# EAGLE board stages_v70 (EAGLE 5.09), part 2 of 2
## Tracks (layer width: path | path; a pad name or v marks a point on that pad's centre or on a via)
+3V3  (via drill 0.5)
  Top 0.254: IC5.19 15.75,59.58 15.86,59.69 18.24,59.69 v18.24,60.48 | v16.49,61.28 15.54,61.28 15.22,61.59 14.3,61.59 C11.1 | 21.73,59.69 | 24.11,61.61 24.05,61.67 IC5.1 | IC5.64 27.21,61.56 C14.1 | v19.51,54.93 v21.73,54.93 | v4.58,51.75 3.79,50.96 3.79,49.53 2.52,48.26 2.52,35.56 1.09,34.13 1.09,30.16 2.52,28.73 3,28.26 3,9.37 | v21.73,54.93 | v21.73,54.93 21.73,59.69 | v1.89,4.13 | v8.39,4.13 8.39,3.02 9.98,1.43 D9.2 | v1.89,4.13 3,5.24 3,9.37 | 3,9.37 | v27.76,56.04 28.75,57.03 R12.2
  Top 0.406: 18.24,59.69 | 18.24,59.69 21.73,59.69 23.65,61.61 24.11,61.61 24.12,61.59 26.02,61.59 26.65,62.23 | 41.92,64.74 v41.89,64.77 41.89,63.31 C10.1 42.49,62.71 C15.1 | v45.7,80.01 45.7,80.64 47.6,82.55 49.51,82.55 49.99,83.03 49.99,89.06 | 49.99,89.06 49.99,90.17 47.45,92.71 44.43,92.71 40.78,89.06 LED9.A | 49.99,89.06 LED8.A | 21.73,92.71 18.08,89.06 LED11.A | 21.73,92.71 | 21.73,92.71 24.59,92.71 28.24,89.06 LED10.A | IC2.3 42.49,58.16 C15.1 | C15.1 42.52,59.41 | 26.65,62.23 C9.1 26.65,62.83 C14.1 | 26.65,62.23 27.38,62.96 L2.2 28.62,63.02 32.84,63.02 33.63,63.82 34.59,63.82 v35.22,64.45
  Bottom 0.254: v16.49,61.28 17.12,61.28 17.92,60.48 v18.24,60.48 | v21.73,54.93 25.54,54.93 26.65,56.04 v27.76,56.04 | LED11.A 16.17,87.79 9.82,87.79 8.55,89.06 LED12.A | 56.65,87.95 58.24,87.95 | v19.51,54.93 17.28,52.7 15.86,52.7 15.22,53.34 6.17,53.34 v4.58,51.75 | v1.89,4.13 v8.39,4.13
  Bottom 0.356: LED10.A
  Bottom 0.406: v35.22,64.45 41.57,64.45 v41.89,64.77 45.7,68.58 v45.7,80.01 | 56.65,87.95 52.84,87.95 LED8.A | 58.24,87.95 59.35,89.06 LED7.A | LED10.A 29.98,87.95 39.19,87.95 LED9.A | LED9.A
+3V3_A  (via drill 0.5)
  Top 0.254: IC5.13 18.05,61.57 16.81,60.33 16.17,60.33 15.92,60.58 IC5.17 13.69,60.58 13.32,60.96 13.03,60.96 C13.1 C12.1 11.06,60.99 10.78,61.28 10.78,62.87 10.41,63.23 IC3.16 9.79,63.85 9.47,64.17 C7.1 9.51,64.81 v9.51,66.04 9.54,66.07 | v14.9,40.48 14.93,40.5 | v14.9,40.48 15.06,40.32 15.08,40.34 IC8.8 | v14.9,40.48 14.92,40.5 | IC10.8 61.11,40.34 60.95,40.5 v60.94,40.48 60.94,41.72 C34.1 | IC5.32 15,53.08 15.38,52.7 15.38,51.44 15.82,50.99 C24.1 | v16.17,53.66 16.17,53.02 15.82,52.67 C24.1 | IC9.8 37.9,40.34 v37.76,40.48 37.76,41.72 C30.1 | C16.1 v10.14,55.09 9.51,55.09 9.03,55.56 8.25,55.56 IC6.16 | v8.24,60.96 8.24,59.85 7.92,59.53 7.92,57.78 7.76,57.63 6.97,57.63 5.7,56.36 5.7,54.29 v5.22,53.82 | v5.22,53.82 | v14.9,40.48 14.9,41.75 | C24.1 15.97,50.95 IC5.33 | C24.1 C26.1 | IC4.2 36.33,54.38 36.33,55.09 36.81,55.56 40.3,55.56 40.62,55.24 C18.1
  Top 0.406: v4.11,99.69 7.6,103.19 v14.9,103.19 v26.33,103.19 v37.76,103.19 v49.19,103.19 v60.62,103.19 | R80.3 41.57,75.98 41.57,87.15 41.1,87.63 40.14,87.63 39.19,88.58 39.19,90.96 37.8,92.35 R86.P$1 | C33.1 14.9,41.75 14.9,41.74 | v8.71,70.64 8.71,69.85 9.98,68.58 9.98,67.97 C5.1 9.95,66.49 9.54,66.07 | R88.P$1 14.9,93.59 14.9,92.55 14.11,91.76 14.11,86.36 14.43,86.04 14.74,86.04 19.19,81.6 19.19,79.53 v18.71,79.06 | v66.02,91.12 66.02,86.2 64.91,85.09 64.91,81.44 64.43,80.96 64.43,79.85 62.84,78.26 59.83,78.26 58.4,76.83 53.95,76.83 53.08,75.96 R79.3 52.98,75.86 51.73,74.61 50.3,74.61 47.29,71.6 47.29,54.61 | v30.14,80.01 29.51,80.64 29.51,85.57 29.98,86.04 29.98,89.38 29.03,90.33 28.4,90.33 26.37,92.35 R87.P$1 | R78.3 61.91,46.02 59.99,47.94 58.56,47.94 58.08,48.42 52.68,48.42 51.28,49.82 C22.1 | C22.1 48.88,51.12 47.29,52.7 47.29,54.61 | C18.1 45.23,54.89 C20.1 45.57,54.61 47.29,54.61 | IC7.1 59.52,49.53 52.53,49.53 51.28,50.77 C22.1
  Bottom 0.254: v9.51,66.04 8.24,64.77 v8.24,60.96 | v16.17,53.66 16.01,53.82 10.14,53.82 | v5.22,53.82 10.14,53.82 | 10.14,53.82 v10.14,55.09
  Bottom 0.406: R89.P$1 3.47,93.67 3.47,99.06 v4.11,99.69 | v49.19,103.19 49.23,103.15 R85.P$1 | R86.P$1 37.76,93.67 v37.76,103.19 | R87.P$1 26.33,93.67 v26.33,103.19 | R88.P$1 14.9,93.67 v14.9,103.19 | v60.62,103.19 60.62,93.67 R84.P$1 60.66,91.72 61.89,90.49 65.39,90.49 v66.02,91.12 | 37.76,42.23 50.62,42.23 51.1,42.7 52.37,42.7 52.84,42.23 60.94,42.23 | 14.9,42.7 v14.9,40.48 | 14.9,42.7 17.76,42.7 18.24,42.23 27.76,42.23 28.24,42.7 29.67,42.7 30.14,42.23 37.76,42.23 | 37.76,42.23 | 37.76,42.23 v37.76,40.48 | 60.94,42.23 v60.94,40.48 | 60.94,42.23 60.94,44.45 61.91,45.42 R78.3 | v8.71,70.64 14.9,70.64 18.71,74.45 18.71,75.94 R82.3 18.69,79.04 v18.71,79.06 | R83.3 8.02,42.7 14.9,42.7 | v30.14,80.01 30.12,79.99 R81.3
ADC_CV_1  (via drill 0.5)
  Top 0.254: v14.9,44.61 14.9,46.35 16.97,48.42 16.97,49.21 17.05,49.3 IC5.34 | v57.13,45.72 59.19,43.66 59.19,43.18 59.51,42.86 R16.1 C35.2 62.21,41.72 62.21,41.27 62.53,40.96 63.48,40.96 63.8,40.64 63.8,40.01 63.49,39.7 IC10.7 | v57.13,45.72
  Bottom 0.254: v14.9,44.61 15.06,44.77 56.18,44.77 v57.13,45.72
ADC_CV_2  (via drill 0.5)
  Top 0.254: v19.19,43.81 17.44,45.56 17.44,49.05 17.55,49.16 IC5.35 | v57.13,44.29 57.76,44.29 58.36,43.69 R14.1 C32.2 58.36,40.8 58.08,40.52 IC10.1
  Bottom 0.254: v19.19,43.81 19.66,44.29 v57.13,44.29
ADC_CV_3  (via drill 0.5)
  Top 0.254: v12.84,49.53 12.36,50.01 12.36,53.82 13.13,54.58 IC5.29 | v40.3,48.58 40.3,45.09 39.07,43.85 R13.1 C31.2 39.07,41.24 39.35,40.96 40.3,40.96 40.62,40.64 40.62,40.01 40.31,39.7 IC9.7
  Bottom 0.254: v12.84,49.53 13.32,49.05 21.41,49.05 21.89,48.58 31.09,48.58 31.57,48.1 33.63,48.1 34.43,47.31 34.9,47.31 35.7,48.1 39.83,48.1 v40.3,48.58
ADC_CV_4  (via drill 0.5)
  Top 0.254: v13.32,50.8 12.84,51.28 12.84,53.66 13.26,54.08 IC5.30 | v34.59,48.42 35.38,47.62 35.38,43.01 35.24,42.86 R15.1 C29.2 35.19,40.8 IC9.1
  Bottom 0.254: v13.32,50.8 14.59,49.53 21.57,49.53 22.05,49.05 31.25,49.05 31.73,48.58 34.43,48.58 v34.59,48.42
ADC_CV_5
  Top 0.254: IC5.27 13.49,55.58 12.86,55.58 11.41,54.13 11.41,45.4 11.41,44.29 | IC8.7 17.45,39.7 17.76,40.01 17.76,40.64 17.44,40.96 16.49,40.96 16.21,41.24 R19.1 C27.2 12.84,42.86 11.89,43.81 | 11.41,44.29 | 11.41,44.29 | 11.41,44.29 | 11.89,43.81 11.41,44.29 | 11.89,43.81
ADC_CV_6
  Top 0.254: IC5.26 13.36,56.08 12.72,56.08 10.93,54.29 10.93,45.24 10.93,44.13 10.93,43.97 11.73,43.18 11.73,42.86 11.73,42.51 C28.2 12.17,42.07 R20.1 12.17,40.65 IC8.1
ADC_SHAPE  (via drill 0.5)
  Top 0.254: 4.16,61.91 IC3.3 4.89,61.93 5.54,61.28 v5.54,59.05 | 15.2,58.08 v15.86,58.74 15.2,58.08 | 15.2,58.08 IC5.22
  Bottom 0.254: v15.86,58.74 5.85,58.74 v5.54,59.05
ADC_TIME_LEVEL  (via drill 0.5)
  Top 0.254: 2.57,54.29 IC6.3 3.17,54.31 3.47,54.61 3.47,55.88 2.84,56.52 v2.84,57.94 | IC5.23 15.42,57.58 16.29,57.58 v17.12,58.42
  Bottom 0.254: v17.12,58.42 16.49,57.78 15.54,57.78 15.06,58.26 6.01,58.26 5.7,57.94 v2.84,57.94
AREF_2.5
  Top 0.254: R40.2 46.81,32.7 46.49,33.02 46.49,36.67 45.7,37.47 45.7,39.69 45.06,40.32 45.06,45.09 45.22,45.24 45.22,46.51 44.59,47.15 43.79,47.15 43.32,47.62 43.32,48.26 41.57,50.01 39.55,52.02 IC4.7
AREF_-2.5  (via drill 0.5)
  Top 0.254: R26.2 41.57,37.78 42.21,37.15 v42.84,37.15 42.84,34.77 41.61,33.53 C41.1 41.1,32.7 39.67,31.27 36.98,31.27 36.82,31.11 IC11.2 35.85,31.28 35.54,31.59 35.54,32.38 35.22,32.7 R33.2 | R24.2 18.71,37.78 19.35,37.15 v19.98,37.15 | v58.88,37.47 64.43,37.47 64.91,37.94 R29.2 | v8.55,39.05 8.55,39.37 9.06,39.88 R23.2 | R33.2 | R22.2 | v31.09,40.8 R22.2 | v54.27,40.8 R21.2
  Bottom 0.254: v8.55,39.05 19.98,39.05 | 19.98,39.05 26.97,39.05 27.92,40.01 29.51,40.01 30.46,39.05 31.09,39.05 | 42.84,39.05 50.14,39.05 51.1,40.01 52.37,40.01 53.32,39.05 54.27,39.05 | 54.27,39.05 56.49,39.05 58.08,37.47 v58.88,37.47 | 42.84,39.05 v42.84,37.15 | 19.98,39.05 v19.98,37.15 | 31.09,39.05 42.84,39.05 | 31.09,39.05 v31.09,40.8 | 54.27,39.05 v54.27,40.8
DAC_1  (via drill 0.5)
  Top 0.254: v43.48,50.48 44.11,49.85 44.11,48.26 45.7,46.67 45.7,45.24 45.86,45.09 46.97,43.97 46.97,39.69 47.6,39.05 47.6,35.24 49.51,33.34 49.51,28.57 47.76,26.83 47.76,25.56 48.4,24.92 48.4,23.97 v48.4,23.34 | R52.2 66.66,25.88 66.66,25.24 v65.86,24.45 | v38.4,56.83 38.4,58.26 38.25,58.41 IC4.10
  Bottom 0.254: v38.4,56.83 37.92,56.36 37.92,53.34 39.83,51.44 41.57,51.44 42.52,50.48 v43.48,50.48 | v48.4,23.34 49.03,22.7 61.89,22.7 63.64,24.45 v65.86,24.45
DAC_2  (via drill 0.5)
  Top 0.254: v48.56,49.85 49.19,49.21 49.19,45.56 49.83,44.93 49.83,42.39 50.46,41.75 50.46,38.26 51.26,37.47 52.68,37.47 53.95,36.2 53.95,34.13 52.21,32.38 51.26,32.38 50.46,31.59 50.46,28.26 49.19,26.99 v49.19,26.35 | v53.95,26.35 R51.2 | v37.45,57.78 37.6,57.94 IC4.11
  Bottom 0.254: v37.45,57.78 37.45,53.18 39.67,50.96 41.41,50.96 42.84,49.53 44.11,49.53 45.22,50.64 47.13,50.64 47.92,49.85 v48.56,49.85 | v53.95,26.35 53.95,26.99 53,27.94 51.1,27.94 49.51,26.35 v49.19,26.35
DAC_3  (via drill 0.5)
  Top 0.254: v46.33,23.81 46.02,24.13 46.02,36.35 45.22,37.15 45.22,39.53 44.59,40.16 44.59,43.66 42.84,45.4 42.84,47.94 41.25,49.53 38.9,51.88 IC4.6 | R53.2 v43.95,23.81
  Bottom 0.254: v43.95,23.81 v46.33,23.81
DAC_4  (via drill 0.5)
  Top 0.254: v26.49,25.72 26.02,26.19 26.02,41.12 28.87,43.97 28.87,46.35 29.67,47.15 30.78,47.15 33.48,49.85 35.38,49.85 37.6,52.07 IC4.4 | v31.73,25.08 31.73,26.04 31.57,26.19 31.57,27.82 R49.2
  Bottom 0.254: v26.49,25.72 26.81,25.4 31.41,25.4 v31.73,25.08
DAC_5  (via drill 0.5)
  Top 0.254: v26.02,24.13 25.54,24.61 25.54,41.43 26.33,42.23 26.33,46.67 27.29,47.62 30.62,47.62 33.32,50.32 35.22,50.32 36.95,52.05 IC4.3 | v21.25,26.67 21.41,26.83 R50.2
  Bottom 0.254: v26.02,24.13 23.95,26.19 23.48,26.67 v21.25,26.67
DAC_6  (via drill 0.5)
  Top 0.254: 32.52,42.7 32.52,44.29 31.41,45.4 31.41,47.15 33.63,49.37 35.54,49.37 38.25,52.09 IC4.5 | v27.13,32.38 26.49,33.02 26.49,40.96 28.24,42.7 29.67,42.7 30.14,42.23 32.05,42.23 32.52,42.7 | 32.52,42.7 | R47.2 8.59,28.89 v7.6,28.89
  Bottom 0.254: v27.13,32.38 12.36,32.38 8.87,28.89 v7.6,28.89
DAC_MOSI  (via drill 0.5)
  Top 0.254: IC5.53 28.07,55.08 28.87,55.88 v29.35,55.88 | v34.27,56.36 35.06,57.15 36.3,58.39 IC4.13
  Bottom 0.254: v34.27,56.36 33.63,55.72 29.51,55.72 v29.35,55.88
DAC_SCK
  Top 0.254: 28.24,54.61 28.55,54.93 29.67,54.93 30.46,55.72 30.46,57.63 31.09,58.26 33.48,58.26 35.22,58.26 35.65,58.69 IC4.14 | 28.24,54.61 | 28.24,54.61 27.71,54.08 IC5.51
DAC_SS  (via drill 0.5)
  Top 0.254: v28.87,53.98 28.48,53.58 IC5.50 | v33.79,53.18 34.96,54.35 IC4.1
  Bottom 0.254: v28.87,53.98 29.67,53.18 v33.79,53.18
GATE_1  (via drill 0.5)
  Top 0.254: IC5.44 v22.05,53.34 | v46.33,49.21 46.33,48.1 46.65,47.78 46.65,45.56 47.92,44.29 47.92,40.01 48.56,39.37 48.56,35.56 v50.94,33.18 | v55.7,33.02 57.13,33.02 58.4,31.75 62.21,31.75 63.16,32.7 66.02,32.7 66.5,32.23 66.5,31.43 67.92,30 67.92,26.99 67.61,26.67 67.61,23.97 66.97,23.34 v66.97,23.02 | v63.64,11.11 63.63,11.12 Q7.C
  Bottom 0.254: v22.05,53.34 22.05,50.48 22.52,50.01 41.1,50.01 42.52,48.58 44.43,48.58 45.06,49.21 v46.33,49.21 | v50.94,33.18 51.1,33.02 v55.7,33.02 | v66.97,23.02 66.34,22.38 66.34,19.84 63.64,17.14 v63.64,11.11
GATE_2  (via drill 0.5)
  Top 0.254: IC5.43 21.57,50.97 21.57,52.07 v21.09,52.55 | v45.38,48.26 46.18,47.47 46.18,45.4 47.45,44.13 47.45,39.85 48.08,39.21 48.08,35.4 49.99,33.5 49.99,28.42 48.24,26.67 48.24,26.04 49.51,24.77 49.51,23.18 47.45,21.11 47.45,19.05 v47.13,18.73 | Q3.C 58.4,15.4 58.24,15.56 58.24,17.78 v57.29,18.73
  Bottom 0.254: v21.09,52.55 21.57,52.07 21.57,50.16 22.21,49.53 31.41,49.53 31.89,49.05 33.95,49.05 34.27,49.37 35.06,49.37 35.22,49.53 40.78,49.53 42.21,48.1 45.22,48.1 v45.38,48.26 | v47.13,18.73 v57.29,18.73
GATE_3  (via drill 0.5)
  Top 0.254: IC5.42 21.05,48.78 21.25,48.58 22.21,48.58 23.79,46.99 23.79,42.7 25.06,41.43 25.06,23.34 25.54,22.86 25.54,22.23 24.11,20.8 24.11,20 23,18.89 23,10 v24.75,8.26 | v31.73,8.26 33,8.26 38.56,8.26 39.35,9.05 Q6.C
  Bottom 0.254: v24.75,8.26 v31.73,8.26
GATE_4  (via drill 0.5)
  Top 0.254: IC5.41 20.55,48.49 20.93,48.1 22.05,48.1 23.32,46.83 23.32,42.55 24.59,41.27 v24.59,22.54 24.59,22.23 | Q4.C | 35.38,15.56 35.55,15.39 Q4.C | 35.38,15.56 | 35.38,15.56 35.38,16.03 35.38,16.35 35.86,16.83 | 35.86,16.83 | 35.86,16.83 35.86,21.91 v34.75,23.02 | v34.75,23.02
  Bottom 0.254: v24.59,22.54 24.9,22.86 34.59,22.86 v34.75,23.02
GATE_5
  Top 0.254: IC5.39 19.55,47.42 19.82,47.15 21.73,47.15 22.36,46.51 22.36,42.23 23.63,40.96 23.63,23.5 23.16,23.02 23.16,20.32 22.36,19.53 21.89,19.05 21.09,18.26 21.09,15.88 21.89,15.08 21.89,8.26 23.16,6.99 23.16,5.71 22.52,5.08 21.25,5.08 20.62,5.71 20.62,6.51 20.62,7 Q5.C
GATE_6  (via drill 0.5)
  Top 0.254: IC5.38 19.05,47.29 19.98,46.35 19.98,45.4 20.62,44.77 21.25,44.77 21.89,44.13 21.89,42.07 23.16,40.8 23.16,24.29 v22.68,23.81 | v13,22.54 13,20.32 13,16.83 12.84,16.67 12.52,16.35 12.52,15.56 | Q2.C 12.69,15.39 12.52,15.56 | 12.52,15.56
  Bottom 0.254: v13,22.54 13.32,22.54 15.54,22.54 16.81,23.81 19.66,23.81 v22.68,23.81
GND  (via drill 0.5)
  Top 0.254: 32.36,26.83 32.36,27.16 32.41,27.16 C52.2 | v65.07,25.4 66.02,26.35 66.02,27.15 | C55.1 65.98,27.3 66.02,27.3
  other vias: 19.51,61.12 12.04,63.5 6.97,69.85 17.28,71.12 26.17,71.12 28.55,66.04 29.19,61.75 7.92,66.2 2.52,49.85 11.41,56.2 14.43,52.07 4.43,18.41 11.57,14.61 9.51,5.4 9.35,26.67 19.82,25.4 31.09,23.81 48.08,33.02 36.49,40.48 13.63,40.48 59.67,40.48 43.95,33.66 49.35,20.32 25.06,43.18 31.41,43.18 36.49,43.18 41.89,43.34 46.02,41.12 46.02,43.34 42.37,41.12 21.73,22.86 46.97,27.15 15.22,31.11 15.22,26.19 27.13,30.48 38.4,26.35 60.3,30.8 60.3,27.94 60.3,23.65 37.13,38.1 14.27,38.1 46.65,37.94 54.59,43.34 53.96,37.62 20.93,43.18 19.35,41.12 28.55,51.59 47.76,48.1 36.02,67.31 40.94,52.39 49.51,71.12 40.62,57.78 49.83,52.39 57.13,60.96 59.35,56.83 34.59,84.61 34.59,80.17 23.16,93.98 34.59,93.66 46.02,93.98 22.84,76.68 55.07,25.56 54.59,23.65 34.27,51.75 24.59,53.66 24.59,55.88 37.45,62.55 48.88,43.34 48.88,41.12 59.67,46.35 57.13,63.5 57.13,66.04 1.25,48.26 1.25,38.1 1.25,27.94 1.25,7.62 8.08,1.27 18.24,1.27 27.13,1.27 37.92,1.27 48.72,1.27 58.24,1.27 67.92,33.02 64.59,1.27 67.77,9.84 67.13,42.7 67.92,78.74 1.25,78.74 67.92,87.31 1.25,87.31 1.25,96.52 67.92,96.52 5.06,105.41 15.22,105.41 25.38,105.41 35.54,105.41 45.7,105.41 55.86,105.41 64.75,105.41 16.17,55.24 21.73,24.77 2.68,59.69 23,58.26 45.86,84.61 23.16,84.61 8.39,87.63 8.24,82.55 9.51,89.53 27.29,86.36 27.92,80.64 45.7,66.04 57.13,54.13 65.23,48.42 57.77,52.86 56.34,52.86 58.4,54.13 4.43,33.66 3.79,44.45 19.66,53.34 19.66,57.78 38.4,23.5 42.84,24.45 39.51,17.14 34.43,14.61 34.43,17.14 25.7,17.14 25.7,15.24 60.3,26.04 46.81,22.38 62.37,17.15 11.57,17.14 16.65,17.14 61.57,9.53 38.4,9.53 15.86,9.53 15.22,23.5 46.02,17.14 46.02,15.24 49.19,17.14 49.19,15.24 57.29,14.61 25.38,20.32 24.27,12.06 57.29,17.14 67.92,18.41 33.63,60.33 59.67,54.13
  pour Top: 69.2,106.68 69.2,0 -0.02,0 -0.02,106.68
  pour Bottom: 69.2,106.68 69.2,0 -0.02,0 -0.02,106.68
LEDS_SCK
  Top 0.254: 38.85,66.67 IC1.3 38.24,66.67 37.29,65.72 37.29,64.45 35.54,62.71 34.11,62.71 33.32,61.91 31.57,61.91 28.24,58.58 28.24,58.1 27.72,57.58 IC5.58
LEDS_SIN
  Top 0.254: IC1.2 38.24,66.04 37.76,65.56 37.76,64.29 35.7,62.23 34.27,62.23 33.48,61.44 31.73,61.44 28.71,58.42 28.71,57.78 28.01,57.08 IC5.57
LEDS_SS
  Top 0.254: 38.86,67.31 IC1.4 38.24,67.31 36.81,65.88 36.81,64.61 35.38,63.18 33.95,63.18 33.16,62.39 31.41,62.39 27.76,58.74 27.76,58.42 27.42,58.08 IC5.59
LEFT_RX  (via drill 0.5)
  Top 0.254: v24.43,59.85 24.69,59.58 IC5.62 | v40.3,67.63 40.3,67.15 41.1,66.36 R7.1
  Bottom 0.254: v24.43,59.85 23.79,60.48 23.79,62.55 25.7,64.45 25.7,65.72 25.7,66.67 27.6,68.58 39.03,68.58 39.98,67.63 v40.3,67.63
LEFT_RX_R
  Top 0.254: JP3.3 55.07,86.68 53,84.61 53,82.07 51.89,80.96 51.89,79.06 49.99,77.15 49.99,75.72 48.56,74.3 46.33,74.3 45.54,73.5 45.54,68.26 43.64,66.36 R7.2
LEFT_TX  (via drill 0.5)
  Top 0.254: 26.21,59.05 IC5.61 24.93,59.08 v24.43,58.58 | v41.1,68.58 41.45,68.23 R5.1
  Bottom 0.254: v41.1,68.58 39.83,68.58 39.35,69.06 27.44,69.06 25.22,66.83 25.22,64.61 23.32,62.71 23.32,62.39 23.32,60.17 23.32,59.37 24.11,58.58 v24.43,58.58
LEFT_TX_R
  Top 0.254: R5.2 43.32,67.47 43.64,67.47 44.11,67.47 45.06,68.42 45.06,73.66 46.18,74.77 48.4,74.77 49.51,75.88 49.51,77.31 51.41,79.22 51.41,81.12 52.53,82.23 52.53,84.77 55.7,87.95 55.7,88.58 56.34,89.22 JP3.2
MORPH_IN
  Top 0.254: R30.2 66.75,38.45 C38.1 66.97,37.47 67.61,36.83 J13.P3
MORPH_IN1
  Top 0.254: J14.P3 51.73,31.27 55.54,35.08 C39.1 56.09,37.88 R28.2
MORPH_IN2
  Top 0.254: R27.2 43.41,38.45 C37.1 43.64,37.78 44.75,36.67 J15.P3
MORPH_IN3
  Top 0.254: J16.P3 28.87,32.23 32.21,35.56 32.36,35.72 C40.1 32.91,37.88 R25.2
MORPH_IN4
  Top 0.254: R31.2 20.55,38.45 C36.1 20.78,37.94 21.89,36.83 J17.P3
MORPH_IN5
  Top 0.254: C42.1 2.42,31.11 J18.P3 6.01,32.23 9.98,36.2 R32.2
N$1
  Top 0.254: J9.P3 44.11,20.32 43.95,20.16 43.95,18.1 43.95,15.24 44.27,14.92 44.27,10.95 43.64,10.32 42.84,10.32 41.57,11.59 41.57,15.24 40.97,15.84 R68.1
N$2
  Top 0.254: 63.32,91.6 LED7.RED_C 60.3,91.6 59.51,92.39 59.19,92.71 58.24,93.66 56.65,93.66 56.02,93.03 55.7,92.71 54.75,91.76 54.75,88.27 51.57,85.09 51.57,82.55 50.46,81.44 50.46,79.53 49.19,78.26 47.29,78.26 40.14,71.12 IC1.10
N$3  (via drill 0.5)
  Top 0.254: IC1.18 32.21,69.22 32.2,69.22 30.94,70.48 30.94,73.34 31.41,73.82 31.41,76.36 30.62,77.15 24.43,77.15 22.84,78.74 22.84,79.38 22.84,81.28 22.21,81.92 19.66,81.92 17.92,83.66 17.92,84.93 17.76,85.09 16.81,85.09 16.01,85.88 16.01,86.2 v15.54,86.68
  Bottom 0.254: v15.54,86.68 13.79,86.68 12.2,85.09 11.25,85.09 9.82,86.52 LED12.GREEN_C
N$4
  Top 0.254: LED8.RED_C 52.84,90.49 52.84,88.27 52.21,87.63 51.26,87.63 50.62,87 50.62,86.2 50.62,82.87 49.67,81.92 47.76,81.92 46.65,80.8 46.65,78.9 46.49,78.74 43.16,75.41 40.23,72.47 40.14,72.39 IC1.12
N$5
  Top 0.254: J10.P3 30.94,14.45 30.94,10.95 31.41,10.48 34.27,10.48 34.59,10.79 34.94,10.79 R76.1
N$6  (via drill 0.5)
  Top 0.254: 34.9,76.68 34.9,75.25 35.38,74.77 35.38,71.44 37.6,69.22 IC1.7 | 34.9,76.68 | v37.76,90.81 38.56,90.01 38.56,88.42 39.35,87.63 39.35,86.2 40.14,85.41 40.14,81.28 36.49,77.63 35.86,77.63 34.9,76.68
  Bottom 0.254: v37.76,90.81 38.56,91.6 LED9.RED_C
N$7
  Top 0.254: R9.2 21.73,69.85 22.93,71.05 Q1.1 23.49,71.08 C3.2
N$8
  Top 0.254: C4.2 17.48,68.65 Q1.3 19.12,68.58 20.3,68.58 20.78,68.1 R8.2
N$9
  Top 0.254: IC1.8 37.6,69.85 35.86,71.6 35.86,74.93 35.38,75.41 35.38,76.52 36.02,77.15 36.65,77.15 40.62,81.12 40.62,86.2 LED9.GREEN_C
N$10
  Top 0.254: LED10.GREEN_C 28.87,80.8 28.87,80.01 29.82,79.06 31.25,79.06 33.32,76.99 33.32,73.5 33.32,73.18 33.45,73.05 IC1.13
N$12
  Top 0.254: 33.4,71.12 IC1.15 32.68,71.12 32.63,71.17 32.36,71.44 32.36,72.87 32.84,73.34 32.84,76.83 31.09,78.58 24.9,78.58 24.27,79.22 24.27,79.85 24.27,81.92 22.84,83.34 20.14,83.34 19.35,84.14 19.35,85.88 19.35,86.04 17.92,87.47 17.12,87.47 16.49,88.11 16.49,90.17 17.44,91.12 LED11.RED_C
N$13
  Top 0.254: R78.B 65.67,44.72 R17.1
N$14
  Top 0.254: IC1.16 32.52,70.48 32.49,70.52 31.89,71.12 31.89,73.03 32.36,73.5 32.36,76.68 30.94,78.11 24.75,78.11 23.79,79.06 23.79,79.69 23.79,81.76 22.68,82.87 19.98,82.87 18.87,83.98 18.87,85.57 17.92,86.52 LED11.GREEN_C
N$15
  Top 0.254: R9.1 21.73,64.45 22.05,64.13 IC5.5
N$16  (via drill 0.5)
  Top 0.254: IC1.17 32.36,69.85 32.34,69.87 31.41,70.8 31.41,73.18 31.89,73.66 31.89,76.52 30.78,77.63 24.59,77.63 23.32,78.9 23.32,79.53 23.32,81.6 22.52,82.39 19.82,82.39 18.39,83.82 18.39,85.09 17.92,85.57 17.28,85.57 16.97,85.57 16.49,86.04 16.49,87.47 15.22,88.74 v15.22,90.65
  Bottom 0.254: v15.22,90.65 14.9,90.33 10.3,90.33 9.03,91.6 LED12.RED_C
N$17
  Top 0.254: J10.P2 31.89,21.11 R61.2
N$18
  Top 0.406: JP5.1 JP5.2 | JP5.1 66.97,58.42 | D2.A 66.34,55.56 JP5.1
N$19
  Top 0.254: J9.P2 36.53,20.36 R63.2
N$20
  Top 0.254: R71.2 39.6,14.64 R68.2 40.46,13.48 Q6.B | R71.2 | R71.2 D5.C
N$21
  Top 0.254: Q4.B 35.22,12.03 R76.2 35.19,11.75 R72.2 D8.C
N$22
  Top 0.254: IC1.11 40.14,71.75 40.21,71.82 43.64,75.25 46.65,78.26 47.13,78.74 48.88,78.74 49.03,78.74 49.99,79.69 49.99,81.6 51.1,82.71 51.1,85.88 LED8.GREEN_C
N$23  (via drill 0.5)
  Top 0.254: R67.1 17.76,16 v17.76,17.78
  Bottom 0.254: v17.76,17.78 20.93,20.95 J11.P3
N$24
  Top 0.254: 7.92,14.61 J12.P3 | 7.92,14.61 | 7.92,14.61 7.92,11.11 8.55,10.48 11.41,10.48 11.6,10.67 R75.1
N$25
  Top 0.254: J12.P2 9.03,21.11 R60.2
N$26
  Top 0.254: J11.P2 13.67,20.36 R64.2
N$27
  Top 0.254: Q5.B 17.6,13.48 R67.2 17.48,14.76 R70.2 | R70.2 | R70.2 D4.C
N$28
  Top 0.254: Q2.B R75.2 13.23,11.87 R74.2 D6.C | D6.C
N$29
  Top 0.254: R8.1 20.78,64.61 21.55,63.84 IC5.6
N$30
  Top 0.254: R16.2 C35.1 64.91,40.29 R29.1 | IC10.6 63.47,39.05 64.12,39.69 64.87,39.69 R29.1 | R29.1 R30.1
N$31
  Top 0.254: IC1.24 33.45,65.1 C8.1 32.96,64.1 32.68,63.82 30.78,63.82 30.62,63.98 30.62,64.16 C6.1 28.63,64.48 L2.1
N$32
  Top 0.254: R14.2 C32.1 57.16,41.19 R21.1 56.78,39.78 R28.1 56.7,39.7 IC10.2 57.9,39.7
N$33
  Top 0.406: L1.2 D1.A
N$34
  Top 0.254: IC9.6 40.29,39.05 40.94,39.69 41.54,39.69 R26.1 | R13.2 C31.1 41.57,40.45 R26.1 | R26.1 R27.1
N$35
  Top 0.406: L4.1 61.89,53.08 C23.1 61.89,52.46 IC7.3
N$36
  Top 0.254: J8.P3 53.8,14.45 53.8,10.95 54.27,10.48 56.49,10.48 56.81,10.79 57.8,10.79 R77.1
N$37
  Top 0.254: R15.2 C29.1 33.99,41.19 R22.1 33.63,40.76 33.63,40.32 33.48,40.16 R25.1 34.67,39.65 IC9.2
N$38
  Top 0.406: C17.1 54.08,56.2 | L5.2 | L5.2 L4.2 62.85,53.72 D2.C 55.7,55.24 55.38,55.56 54.72,55.56 C17.1 | L3.1 52.18,56.01 C17.1
N$39
  Top 0.254: IC8.6 16.68,39.05 17.44,39.05 18.04,39.65 R24.1 | R24.1 18.71,40.45 R19.2 C27.1 | R31.1 R24.1
N$41
  Top 0.254: 10.78,39.69 10.78,39.37 10.42,39.02 R32.1 | 10.78,39.69 10.78,40.64 10.97,40.83 R20.2 | IC8.2 11.86,39.69 10.78,39.69 | R20.2 10.78,41.08 R23.1 | R20.2 10.78,41.47 10.78,41.59 10.65,41.72 C28.1
N$43
  Top 0.254: IC1.14 34.11,71.75 34.43,72.07 34.43,72.87 33.79,73.5 33.79,77.15 33.48,77.47 33.48,80.64 32.68,81.44 30.14,83.98 30.14,85.25 30.62,85.72 30.62,89.69 28.87,91.44 LED10.RED_C
N$46
  Top 0.254: J8.P2 54.75,21.11 R62.2
N$47
  Top 0.254: J7.P2 59.39,20.36 R65.2
N$48
  Top 0.254: IC6.1 2,55.61 1.73,55.88 1.73,71.91 2.2,72.39 3.47,73.66 3.47,78.11 4.74,79.38 4.74,79.69 4.74,80.8 1.41,84.14 1.41,85.72 2.2,86.52 2.2,91.44 1.41,92.23 1.41,94.77 2.36,95.73 9.98,95.73 11.89,97.63 64.59,97.63 67.29,94.93 67.29,88.27 66.97,87.95 66.97,87.63 66.97,86.04 67.29,85.72 67.77,85.25 67.77,82.39 66.81,81.44 65.7,81.44 65.07,80.8 65.07,79.69 63,77.63 60.3,77.63 59.67,76.99 59.67,76.22 R78.2
N$49
  Top 0.254: R83.B 8.43,44.63 R18.1
N$50
  Top 0.254: D3.C R69.2 63.2,14.92 R66.2 63.32,13.48 Q7.B
N$51
  Top 0.254: R83.2 2.52,75.7 2.52,73.34 1.73,72.55 1.25,72.07 1.25,55.56 1.85,54.96 IC6.2
N$52
  Top 0.254: Q3.B 58.08,12.03 R77.2 58.05,11.75 R73.2 D7.C
N$53  (via drill 0.5)
  Top 0.254: IC6.12 8.22,53.02 8.87,53.02 9.03,52.86 9.03,50.64 8.87,50.48 6.65,50.48 5.38,49.21 5.38,47.15 6.01,46.51 6.01,46.2 6.81,45.4 v7.92,45.4
  Bottom 0.254: R82.2 21.09,46.06 21.09,46.83 20.78,47.15 9.35,47.15 8.55,46.35 8.55,46.04 v7.92,45.4
N$54  (via drill 0.5)
  Top 0.254: IC6.13 9.03,53.66 9.51,53.18 9.51,50.48 9.03,50.01 6.81,50.01 5.85,49.05 5.85,47.62 v6.97,46.51
  Bottom 0.254: R81.2 31.81,45.96 30.62,47.15 21.41,47.15 20.93,47.62 9.19,47.62 8.08,46.51 v6.97,46.51
N$55  (via drill 0.5)
  Top 0.254: IC6.14 8.22,54.29 9.03,54.29 9.98,53.34 9.98,50.32 9.19,49.53 6.97,49.53 6.33,48.9 6.33,47.94 6.81,47.47 v7.76,47.47
  Bottom 0.254: R80.2 44.05,46.57 43.48,47.15 36.02,47.15 35.22,46.35 34.11,46.35 33.32,47.15 31.25,47.15 30.78,47.62 21.57,47.62 21.09,48.1 8.55,48.1 7.92,47.47 v7.76,47.47
N$56  (via drill 0.5)
  Top 0.254: IC6.15 8.23,54.93 9.03,54.93 10.46,53.5 10.46,49.53 9.51,48.58 v7.28,48.58 | v7.28,48.58 | v7.28,48.58 | v7.28,48.58 | v7.28,48.58
  Bottom 0.254: R79.2 55.48,46.73 55.07,47.15 44.11,47.15 43.64,47.62 35.86,47.62 35.06,46.83 34.27,46.83 33.48,47.62 31.41,47.62 30.94,48.1 21.73,48.1 21.25,48.58 v7.28,48.58 | v7.28,48.58
N$57  (via drill 0.5)
  Top 0.254: 63.36,16.03 R66.1 64.4,16 v64.59,16.19
  Bottom 0.254: v64.59,16.19 64.59,17.46 67.61,20.48 J7.P3
N$58
  Top 0.254: R85.P$2 51.73,95.25 50.3,96.68 12.2,96.68 9.98,94.46 9.98,92.23 9.66,91.92 9.03,91.92 8.08,91.92 6.65,90.49 5.7,90.49 5.06,89.85 5.06,85.72 6.17,84.61 6.17,79.85 6.17,79.53 8.55,77.15 8.87,77.15 10.46,77.15 10.93,76.68 10.93,75.41 10.3,74.77 9.03,74.77 8.39,74.14 6.81,74.14 6.17,73.5 5.22,73.5 3.63,71.91 3.15,71.44 3.15,62.87 3.44,62.58 IC3.2
N$59
  Top 0.254: 3.15,72.07 5.06,73.98 6.01,73.98 6.65,74.61 8.08,74.61 8.55,75.09 8.55,76.36 5.7,79.22 5.7,79.69 5.7,84.45 4.58,85.57 4.58,91.6 6.01,93.03 R89.P$2 | 3.15,72.07 | 3.15,72.07 2.68,71.6 2.68,61.75 3.15,61.28 IC3.4
N$60
  Top 0.254: R86.P$2 40.3,95.09 39.19,96.2 12.36,96.2 10.46,94.3 10.46,92.08 9.82,91.44 9.19,91.44 6.97,89.22 6.97,85.72 6.65,85.41 6.65,81.6 6.65,80.49 | 10.62,77.63 11.41,76.83 11.41,75.25 10.46,74.3 9.19,74.3 8.55,73.66 6.97,73.66 6.33,73.03 5.38,73.03 4.11,71.75 3.63,71.28 3.63,63.98 4.14,63.47 IC3.1 | 6.65,80.49 6.65,80.01 | 10.62,77.63 | 10.62,77.63 8.71,77.63 6.65,79.69 6.65,80.49
N$61
  Top 0.254: R87.P$2 28.87,94.61 27.76,95.73 13.95,95.73 13,94.77 13,92.23 13,86.04 13,85.88 12.04,84.93 11.73,84.61 11.73,78.42 12.04,78.11 13,77.15 14.27,77.15 14.9,76.52 14.9,76.36 14.9,75.41 14.27,74.77 12.84,74.77 10.93,72.87 9.66,72.87 9.03,72.23 7.44,72.23 6.81,71.6 5.85,71.6 5.54,71.28 5.54,66.67 6.17,66.04 6.17,63.02 7.28,61.91 9.78,61.91 | 9.78,61.91 IC3.14 9.78,61.91
N$62
  Top 0.254: 9.76,62.55 IC3.15 | 9.76,62.55 IC3.15 | R88.P$2 17.44,94.61 17.12,94.93 13.79,94.93 13.47,94.61 13.47,88.11 13.47,85.88 13.47,85.72 | 13.47,85.72 | 13.47,85.72 | 13.47,85.72 12.52,84.77 12.2,84.45 12.2,78.58 12.52,78.26 13.16,77.63 14.43,77.63 15.38,76.68 15.38,76.04 15.38,75.25 14.43,74.3 13,74.3 11.09,72.39 9.82,72.39 9.19,71.75 7.6,71.75 6.97,71.12 6.17,71.12 6.01,70.96 6.01,69.69 6.01,66.83 6.65,66.2 6.65,63.34 7.44,62.55 9.76,62.55 | 9.76,62.55 IC3.15
N$63
  Top 0.254: 4.12,60.64 IC3.5 3.17,60.63 2.2,61.59 2.2,71.75 2.68,72.23 4.9,74.45 5.54,74.45 6.01,74.93 6.01,76.36 5.22,77.15 5.22,84.3 2.68,86.84 2.68,87.63 | 1.89,92.39 1.89,94.61 2.52,95.25 10.14,95.25 12.04,97.16 60.94,97.16 63.16,94.93 R84.P$2 | 2.68,87.63 2.68,87.15 | 2.68,87.63 2.68,91.6 1.89,92.39 | 1.89,92.39
N$64  (via drill 0.5)
  Top 0.254: R4.1 | R4.1 13.16,72.55 13.32,72.71 v13.32,73.34
  Bottom 0.254: v13.32,73.34 13.69,73.72 R82.B
N$65
  Top 0.254: R39.2 64.27,31.22 C49.2 64.24,30.48 63.48,30.48 63.02,30.02 IC14.14 62.32,29.89 62.05,30.16 61.26,30.16 60.78,29.69 60.78,28.73 62.22,27.29 IC14.10
N$66
  Top 0.254: R39.1 65.39,31.38 R46.1 66.85,30.45 67.45,29.84 67.45,27.15 67.13,26.83 67.13,24.45 66.02,23.34 66.02,19.21 66.02,19.05 66.66,18.41 66.66,15.56 67.45,14.76 67.45,11.11 66.66,10.32 66.66,8.73 67.61,7.78 J1.P3
N$67
  Top 0.254: 48.08,21.11 49.19,22.23 50.46,23.5 50.46,27.3 50.94,27.78 50.94,29.53 51.26,29.84 52.21,29.84 52.81,30.45 R45.1 55.22,31.22 55.07,31.38 R37.1 | J2.P3 51.73,3.17 48.08,6.83 48.08,21.11 | 48.08,21.11
N$68
  Top 0.254: R6.1 32.08,66.04 IC1.23
N$69
  Top 0.254: J4.P3 28.87,3.17 26.02,6.03 26.02,12.06 24.59,13.49 24.59,17.78 26.49,19.68 26.49,21.75 27.6,22.86 27.6,24.77 28.24,25.4 30.3,25.4 31.09,26.19 31.09,27.15 30.94,27.3 30.94,29.69 31.7,30.45 R43.1 33.32,31.22 R36.1
N$70
  Top 0.254: R49.1 32.08,29.53 32.68,29.53 32.96,29.25 R43.2 C46.1 34.46,29.21 34.49,29.24 IC13.2
N$71
  Top 0.254: R51.1 54.02,29.25 R45.2 C48.1 56.37,29.21 56.4,29.24 IC14.2
N$72
  Top 0.254: R53.1 43.95,26.83 44.43,27.3 44.43,28.57 43.79,29.21 43.51,29.21 R44.2 C47.1 42.33,29.21 42.3,29.24 IC13.13
N$73
  Top 0.254: C49.1 R46.2 65.45,29.18 R52.1 | C49.1 64.24,29.21 | IC14.13 C49.1
N$74
  Top 0.254: R38.1 43.48,31.38 R44.1 44.15,30.45 44.91,29.69 44.91,22.7 46.02,21.59 46.02,20.32 44.75,19.05 J3.P3
N$75
  Top 0.254: LED1.2 66.18,12.54 65.23,13.49 65.23,14.76 65.7,15.24 65.7,18.1 65.07,18.73 65.07,22.7 63,24.77 R59.1 62.02,26.32 62.34,26.64 IC14.9
N$76
  Top 0.254: LED1.1 66.18,18.26 65.54,18.89 65.54,22.88 63.02,25.4 IC14.8
N$77
  Top 0.254: R38.2 42.37,31.22 C47.2 42.33,30.48 41.57,30.48 41.11,30.02 IC13.14 40.42,29.89 40.14,30.16 39.19,30.16 38.87,29.84 38.87,28.73 39.03,28.57 40.32,27.29 IC13.10
N$78
  Top 0.254: LED2.2 43.32,12.54 42.37,13.49 42.37,15.24 | 42.37,23.02 40.46,24.92 40.27,24.92 R57.1 40.11,26.16 40.59,26.64 IC13.9 | 42.37,15.24 | 42.37,15.24 42.84,15.72 42.84,22.54 42.37,23.02 | 42.37,23.02
N$79
  Top 0.254: IC13.8 41.11,24.91 42.84,23.18 43.32,22.7 LED2.1
N$80
  Top 0.254: R37.2 56.34,31.38 C48.2 56.99,30.45 57.54,29.89 IC14.1 58.29,29.89 58.56,30.16 59.35,30.16 59.83,29.69 59.83,28.73 58.38,27.29 IC14.5
N$81
  Top 0.254: LED5.2 54.75,12.54 56.02,13.81 56.02,14.13 56.02,23.5 57.29,24.77 R58.1 58.59,26.32 58.27,26.64 IC14.6
N$82
  Top 0.254: IC14.7 57.59,25.7 55.54,23.65 55.54,15.08 55.54,14.76 LED5.1
N$83
  Top 0.254: C46.2 34.46,30.48 34.9,30.48 35.49,29.89 IC13.1 36.38,29.89 36.65,30.16 37.6,30.16 37.92,29.84 37.92,28.73 36.49,27.3 35.7,27.3 IC13.5 | C46.2 34.39,30.48 | R36.2 34.43,31.38 C46.2
N$84
  Top 0.254: LED3.2 31.89,12.54 33.16,13.81 33.16,23.34 34.43,24.61 36.53,24.61 R56.1 36.69,26.32 36.36,26.64 IC13.6
N$85
  Top 0.254: LED3.1 32.68,14.76 32.68,23.65 35.02,25.99 IC13.7
N$86
  Top 0.254: J6.P3 6.01,2.7 3.47,5.24 3.47,10.48 3.47,26.19 7.72,30.45 R41.1 10.14,31.22 R35.1
N$87
  Top 0.254: C44.1 R41.2 10.11,29.25 9.51,29.84 8.91,29.84 R47.1 | C44.1 | C44.1 | C44.1 IC12.2
N$88
  Top 0.254: C45.1 19.15,29.21 | C45.1 R42.2 20.37,29.18 R50.1 | IC12.13 C45.1
N$89
  Top 0.254: R34.1 20.3,31.22 R42.1 20.34,30.48 21.89,30.48 22.21,30.16 22.21,26.19 21.73,25.72 21.41,25.72 20.62,24.92 20.62,19.53 20.62,18.73 20.62,18.57 20.62,15.72 21.41,14.92 21.41,6.83 J5.P3
N$90
  Top 0.254: R34.2 19.19,31.38 C45.2 18.54,30.45 17.98,29.89 IC12.14 17.24,29.89 16.97,30.16 16.17,30.16 15.7,29.69 15.7,28.73 17.14,27.29 IC12.10
N$91
  Top 0.254: 19.51,13.49 20.46,12.54 LED6.2 | 19.51,13.49 | 19.51,13.49 19.51,23.34 18.08,24.77 R55.1 16.93,26.32 17.25,26.64 IC12.9
N$92
  Top 0.254: IC12.8 17.94,25.7 19.98,23.65 19.98,19.68 19.98,18.41 | 19.98,18.41 | 19.98,18.41 19.98,14.45 LED6.1
N$93
  Top 0.254: R35.2 11.25,31.38 C44.2 11.29,30.48 11.73,30.48 12.32,29.89 IC12.1 13.2,29.89 13.47,30.16 14.43,30.16 14.74,29.84 14.74,28.73 13.32,27.3 12.52,27.3 IC12.5
N$94
  Top 0.254: LED4.2 9.03,12.54 10.3,13.81 10.3,23.18 11.89,24.77 R54.1 13.51,26.32 13.19,26.64 IC12.6
N$95
  Top 0.254: LED4.1 9.82,14.76 9.82,23.34 12.5,26.02 IC12.7
N$96
  Top 0.406: JP5.10 JP5.9 66.72,68.96 66.49,69.19 D1.C
N$99
  Top 0.406: 57.03,69.75 IC2.1 56.89,68.34 50.14,61.59 50.14,56.24 L3.2 49.51,56.2 48.88,55.56 48.88,54.16 C19.1
N$100
  Top 0.254: R81.B 27.64,73.44 R2.1
N$101
  Top 0.254: IC1.9 40.14,70.48 47.45,77.79 49.35,77.79 50.94,79.38 50.94,81.28 52.05,82.39 52.05,84.93 55.22,88.11 55.22,91.6 56.81,93.19 58.08,93.19 58.88,92.39 62.21,89.06 | 62.21,89.06 | 62.21,89.06 62.21,87.31 63,86.52 LED7.GREEN_C
N$102
  Top 0.254: R80.B 38.32,75.96 39.31,74.97 R1.1
N$103
  Top 0.254: R79.B 46.25,75.96 44.39,74.1 R3.1
NORMALIZATION_PROBE  (via drill 0.5)
  Top 0.254: D9.3 13.32,2.39 13.49,2.22 16.49,2.22 18.87,4.6 22.68,4.6 23.63,5.56 23.63,7.3 22.36,8.57 22.36,15.24 22.05,15.56 v22.05,16.19 | v22.05,16.19 22.05,16.51 22.05,18.57 23.63,20.16 23.63,22.86 24.11,23.34 24.11,35.24 24.11,41.12 22.84,42.39 22.84,44.93 22.84,46.67 21.89,47.62 20.78,47.62 20.05,48.35 IC5.40 | 9.03,16.67 R60.1 | 9.03,16.67 8.71,16.35 9.03,16.67 | v8.55,16.19 9.03,16.67 | v22.05,16.19 22.05,15.72 v22.05,16.19 | R63.1 37.76,16.86 v37.76,17.94 | v53.95,16.19 54.75,16.99 R62.1 | v31.09,16.19 31.89,16.99 R61.1 | v60.78,18.26 60.59,18.06 R65.1 | R64.1 14.9,16.86 v14.9,18.1
  Bottom 0.254: 14.9,16.19 21.89,16.19 v22.05,16.19 26.97,16.19 27.92,15.24 30.14,15.24 v31.09,16.19 37.45,16.19 37.76,16.19 | 14.9,16.19 v8.55,16.19 | 37.76,16.19 v37.76,17.94 | 37.76,16.19 49.83,16.19 50.78,15.24 53,15.24 v53.95,16.19 58.56,16.19 58.72,16.19 v60.78,18.26 | 14.9,16.19 v14.9,18.1
POTS_ADDR_A
  Top 0.254: 8.23,52.39 IC6.11 | 8.23,52.39 8.24,52.39 | 8.23,52.39 7.28,52.39 7.12,52.55 7.12,55.88 7.44,56.2 8.08,56.2 8.39,56.2 9.35,57.15 9.35,58.1 9.79,58.55 IC3.9 11.15,58.68 11.25,58.58 IC5.21
POTS_ADDR_B
  Top 0.254: IC6.10 7.01,51.71 6.65,52.07 6.65,56.04 7.28,56.67 7.44,56.67 8.24,56.67 8.87,57.31 8.87,59.05 9.19,59.37 9.75,59.37 IC3.10 9.84,59.37 11.41,59.37 11.7,59.08 IC5.20
POTS_ADDR_C
  Top 0.254: IC5.18 11.17,60.08 11.09,60.01 9.82,60.01 IC3.11 9.76,60.01 9.03,60.01 8.39,59.37 8.39,57.47 8.08,57.15 7.12,57.15 6.17,56.2 6.17,51.75 6.81,51.12 8.14,51.12 IC6.9
RESET  (via drill 0.5)
  Top 0.254: v21.25,60.96 21.05,61.16 IC5.7 | R12.1 30.97,59.53 JP6.4
  Bottom 0.254: v21.25,60.96 21.25,58.58 22.52,57.31 28.08,57.31 30.3,59.53 JP6.4
RIGHT_RX  (via drill 0.5)
  Top 0.254: v17.92,56.2 16.81,56.2 16.42,56.58 IC5.25 | v4.74,55.4 3.95,56.2 3.95,57.15 3.95,57.31 4.58,57.94 5.7,57.94 6.49,58.74 6.49,59.37 6.01,59.85 6.01,61.28 6.01,61.44 5.06,62.39 5.06,63.5 4.43,64.14 R10.1
  Bottom 0.254: v17.92,56.2 16.81,56.2 16.17,56.83 15.22,56.83 14.74,57.31 13.16,57.31 6.65,57.31 v4.74,55.4
RIGHT_RX_R
  Top 0.254: R10.2 4.43,66.2 4.11,66.52 4.11,71.12 5.54,72.55 6.49,72.55 7.12,73.18 8.71,73.18 9.35,73.82 10.62,73.82 11.89,75.09 11.89,76.99 10.78,78.11 8.87,78.11 7.12,79.85 7.12,83.5 7.12,85.25 7.44,85.57 7.44,87.95 8.08,88.58 10.14,88.58 10.62,89.06 JP4.2
RIGHT_TX  (via drill 0.5)
  Top 0.254: v4.9,56.99 5.54,56.99 6.97,58.42 6.97,59.53 6.49,60.01 6.49,61.59 5.54,62.55 5.54,63.66 5.38,63.82 R11.1 | v17.12,57.15 17.06,57.08 IC5.24
  Bottom 0.254: v17.12,57.15 16.97,57.31 15.38,57.31 14.9,57.78 6.33,57.78 5.54,56.99 v4.9,56.99
RIGHT_TX_R
  Top 0.254: R11.2 5.38,66.2 4.58,66.99 4.58,70.96 5.7,72.07 6.65,72.07 7.28,72.71 8.87,72.71 9.51,73.34 10.78,73.34 12.36,74.93 12.36,77.15 11.25,78.26 11.25,84.77 11.73,85.25 JP4.3
STAGE_LED_1  (via drill 0.5)
  Top 0.254: v50.78,48.26 51.89,47.15 56.02,47.15 56.49,46.67 57.61,46.67 58.08,46.2 58.08,45.72 59.99,43.81 64.12,43.81 64.47,43.46 R17.2 | v25.22,51.44 25.22,50.48 24.59,49.85 22.84,49.85 22.55,50.14 IC5.45
  Bottom 0.254: v25.22,51.44 26.17,50.48 41.25,50.48 42.68,49.05 44.27,49.05 45.38,50.16 46.97,50.16 49.51,47.62 50.14,47.62 v50.78,48.26
STAGE_LED_2  (via drill 0.5)
  Top 0.254: v23.95,64.61 23.55,64.21 IC5.2 | v40.3,69.53 40.3,70.01 41.89,71.6 42.05,71.75 R3.2
  Bottom 0.254: v40.3,69.53 39.98,69.53 39.67,69.53 27.29,69.53 24.75,66.99 24.75,65.41 v23.95,64.61 | v23.95,64.61
STAGE_LED_3  (via drill 0.5)
  Top 0.254: v23.79,65.88 23.05,65.14 IC5.3 | v37.13,72.39 37.13,73.5 37.6,73.98 R1.2
  Bottom 0.254: v23.79,65.88 24.27,66.36 24.27,67.31 26.97,70.01 36.02,70.01 37.13,71.12 v37.13,72.39
STAGE_LED_4  (via drill 0.5)
  Top 0.254: IC5.4 22.55,66.23 v23.32,66.99 | 28.87,72.2 R2.2 28.84,71 v28.87,70.96
  Bottom 0.254: v23.32,66.99 26.81,70.48 28.4,70.48 28.71,70.8 v28.87,70.96
STAGE_LED_5
  Top 0.254: R4.2 | R4.2 13.16,68.74 13.47,68.42 13.47,66.52 16.55,63.44 IC5.16
STAGE_LED_6  (via drill 0.5)
  Top 0.254: IC5.28 13,55.09 11.89,53.98 11.89,45.09 v12.68,44.29 | 9.68,44.28 v9.66,44.29 9.63,44.26 R18.2
  Bottom 0.254: v9.66,44.29 v12.68,44.29
SW_MODE_1  (via drill 0.5)
  Top 0.254: IC5.8 20.55,64.04 19.19,65.41 18.55,65.41 16.33,67.63 16.33,71.91 18.71,74.3 | 18.71,74.3 19.35,74.3 20.3,75.25 20.3,76.68 19.35,77.63 18.39,77.63 17.44,78.58 17.44,80.33 v17.92,80.8 | 18.71,74.3
  Bottom 0.254: SW1.4 SW1.3 59.87,84.65 58.56,83.34 46.97,83.34 46.49,82.87 36.97,82.87 36.17,82.07 25.38,82.07 25.06,81.76 18.87,81.76 | 18.87,81.76 | v17.92,80.8 18.87,81.76
SW_MODE_2  (via drill 0.5)
  Top 0.254: IC5.9 20.05,63.91 19.03,64.93 18.39,64.93 15.86,67.47 15.86,72.07 18.55,74.77 19.19,74.77 19.82,75.41 19.82,76.52 19.19,77.15 18.08,77.15 16.97,78.26 16.97,81.6 v17.12,81.76
  Bottom 0.254: SW2.4 SW2.3 47.53,84.65 46.22,83.34 36.65,83.34 35.86,82.55 25.06,82.55 24.75,82.23 17.6,82.23 v17.12,81.76
SW_MODE_3  (via drill 0.5)
  Top 0.254: v15.86,82.23 15.86,81.76 16.49,81.12 16.49,78.11 17.28,77.31 17.28,74.14 16.17,73.03 | IC5.10 19.55,63.77 18.87,64.45 18.24,64.45 15.38,67.31 15.38,72.23 16.17,73.03 | 16.17,73.03 | 16.17,73.03
  Bottom 0.254: SW3.4 SW3.3 35.58,83.19 24.9,83.19 24.43,82.71 16.33,82.71 v15.86,82.23
SW_MODE_4  (via drill 0.5)
  Top 0.254: v15.06,83.19 14.74,82.87 14.74,82.07 16.01,80.8 16.01,77.95 16.81,77.15 16.81,74.3 15.7,73.18 | v15.06,83.19 | 16.65,65.41 18.08,63.98 18.71,63.98 19.05,63.64 IC5.11 | 16.65,65.41 | 15.7,73.18 | 16.65,65.41 14.9,67.15 14.9,72.39 15.7,73.18 | 15.7,73.18
  Bottom 0.254: SW4.4 SW4.3 24.15,83.19 v15.06,83.19
SW_MODE_5
  Top 0.254: SW5.3 14.19,81.99 15.54,80.64 15.54,77.79 16.33,76.99 16.33,74.77 16.33,74.45 14.43,72.55 14.43,66.83 16.33,64.93 17.55,63.71 IC5.14
  Bottom 0.254: SW5.3 SW5.4
SW_MODE_6  (via drill 0.5)
  Top 0.254: v13.16,81.92 12.68,81.44 12.68,78.74 13.32,78.11 14.59,78.11 15.86,76.83 15.86,74.61 15.06,73.82 | IC5.15 17.05,63.58 13.95,66.67 13.95,72.71 15.06,73.82 | 14.74,73.5 | 15.06,73.82 14.74,73.5 | 15.06,73.82
  Bottom 0.254: SW6.3 SW6.4 9.31,84.65 12.04,81.92 v13.16,81.92
SWCLK
  Top 0.254: JP6.3 31.81,56.44 30.3,54.93 30.3,53.98 29.41,53.08 IC5.49
SWDIO
  Top 0.254: IC5.46 23.05,51.96 23.63,52.55 29.67,52.55 31.57,54.45 JP6.2
VCC  (via drill 0.5)
  Top 0.254: v10.78,26.67 11.38,27.27 C50.1 IC12.4 | v33.63,26.67 34.39,27.43 C52.1 IC13.4 | v55.7,26.67 55.86,26.67 56.46,27.27 C54.1 IC14.4
  Top 0.406: C25.1 | C25.1 C21.1 63.98,52.23 64.43,52.23 65.65,53.45 L5.1 | v63.8,48.26 63.83,48.29 C25.1
  Bottom 0.254: 33.63,28.57 17.44,28.57 17.12,28.26 12.36,28.26 v10.78,26.67 | v55.7,26.67 53.8,28.57 48.88,28.57 48.56,28.26 47.76,28.26 47.45,28.57 40.62,28.57 40.3,28.26 36.49,28.26 36.17,28.57 33.63,28.57 | 33.63,28.57 v33.63,26.67
  Bottom 0.406: v55.7,26.67 56.02,26.99 56.34,26.99 62.37,26.99 63.16,26.99 65.07,28.89 65.07,37.15 64.43,37.78 64.43,47.47 63.8,48.1 v63.8,48.26
VEE  (via drill 0.5)
  Top 0.254: v27.44,27.46 27.92,27.46 28.4,27.94 29.82,27.94 30.46,28.57 30.46,30.48 31.09,31.11 31.57,31.11 32.05,31.59 32.05,32.23 32.52,32.7 R33.1 | 19.17,26.68 v19.19,26.67 19.07,26.79 C51.2 IC12.11 | v42.37,26.67 42.4,26.7 C53.2 IC13.11 | v65.07,26.67 64.75,26.67 64.15,27.27 C55.2 IC14.11
  Top 0.406: v58.08,72.39 58.4,72.39 59.03,73.03 L1.1 | v58.08,72.39 57.95,72.26 | 53.82,71.12 C2.2 54.91,71.12 55.54,71.75 56.49,71.75 | 56.49,71.75 57.45,71.75 v58.08,72.39 | C1.2 56.49,73.16 56.49,71.75
  Bottom 0.254: 42.37,25.4 47.92,25.4 48.56,24.77 50.14,24.77 50.78,25.4 52.37,25.4 53.16,24.61 | 53.16,24.61 | 53.16,24.61 57.29,24.61 57.45,24.77 62.37,24.77 64.27,26.67 v65.07,26.67 | 42.37,25.4 v42.37,26.67 | v19.19,26.67 20.46,27.94 27.44,27.94 | 27.44,27.94 30.78,27.94 33.32,25.4 42.37,25.4 | 27.44,27.94 v27.44,27.46
  Bottom 0.406: v65.07,26.67 65.7,27.3 65.7,37.47 65.07,38.1 65.07,46.51 67.61,49.05 67.61,71.12 66.34,72.39 v58.08,72.39
VREF_BIAS  (via drill 0.5)
  Top 0.254: v48.08,29.21 47.76,29.53 47.76,29.69 C43.1 R40.1 R48.2 | R48.2 | v16.65,29.21 17.27,28.59 IC12.12 | v39.83,29.21 40.45,28.59 IC13.12 | v13.79,29.21 13.17,28.59 IC12.3 | v58.88,29.21 58.26,28.59 IC14.3 | v61.73,29.21 62.35,28.59 IC14.12 | v36.97,29.21 36.35,28.59 IC13.3
  Bottom 0.254: v13.79,29.21 v16.65,29.21 v36.97,29.21 v39.83,29.21 v48.08,29.21 v58.88,29.21 v61.73,29.21

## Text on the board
tPlace: TX | < | RX | > | RX | TX | Red stripe
tNames: Stages | v7 cc-by-sa Émilie Gillet 2017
